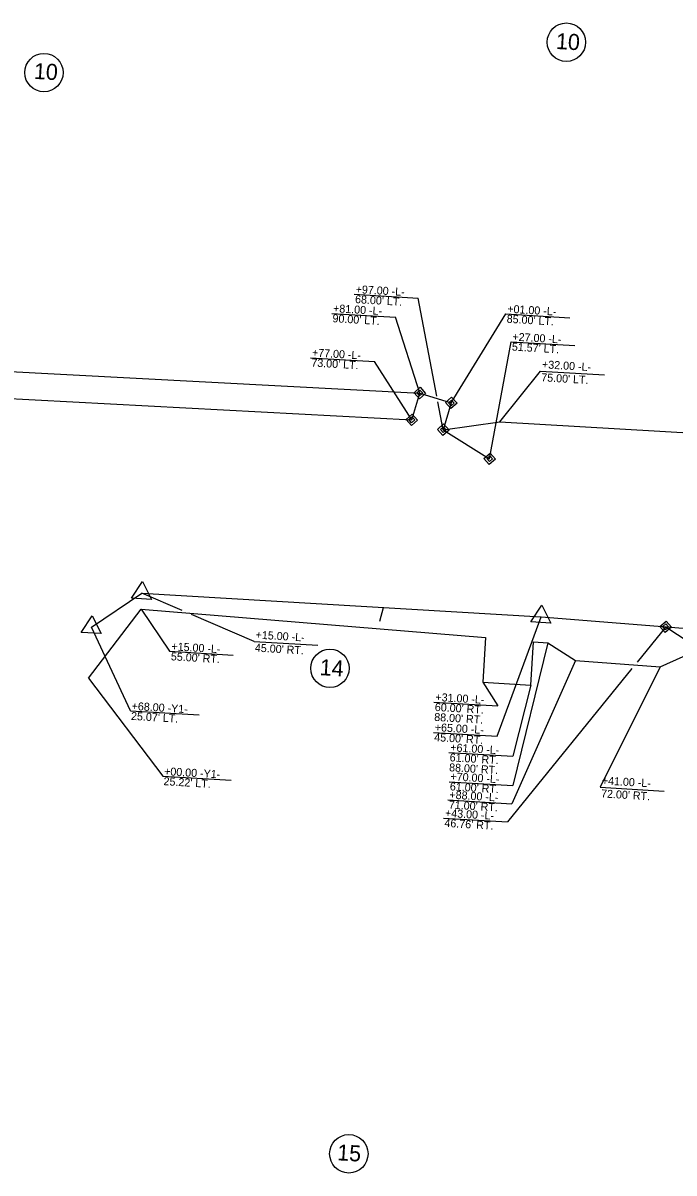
# Model space of a CAD drawing. Extents: x 2010883 to 2014849, y 442000 to 447413.
# Drawn here: x 2012375 to 2012782, y 444554 to 445272 of the extents above; entities that cross this region are included whole.
import ezdxf

# ---------------------------------------------------------------- set-up
doc = ezdxf.new("R2010")
doc.units = 0
for name, color, linetype in [('Old_Level_29', 7, 'Continuous'), ('Prop Easement Construction', 7, 'Continuous'), ('Prop Easement Construction Station Offsets', 7, 'Continuous'), ('Prop Easement Permanent Utility', 7, 'Continuous'), ('Prop Easement Permanent Utility Station Offsets', 7, 'Continuous'), ('Prop Parcel Number CELL', 7, 'Continuous'), ('Prop Parcel Number Text', 7, 'Continuous'), ('Prop ROW Marker CELL', 7, 'Continuous'), ('Prop ROW Permanent Easement CELL', 7, 'Continuous'), ('Prop ROW RW Lines', 7, 'Continuous'), ('Prop ROW Station Offsets', 7, 'Continuous')]:
    doc.layers.add(name, color=color, linetype=linetype)

msp = doc.modelspace()

# ---------------------------------------------------------------- linework, layer by layer
at = {"layer": 'Old_Level_29'}
msp.add_line((2012598.25, 444898.78), (2012600.7, 444907.31), dxfattribs=at)
at = {"layer": 'Prop Easement Construction'}
for p, q in [((2012296.76, 445058.46), (2012623.31, 445041.21)), ((2012637.99, 445018.31), (2012673.34, 445023.24)), ((2012673.34, 445023.24), (2012962.84, 445006.17)), ((2012416.2, 444862.98), (2012449.07, 444906.23)), ((2012449.07, 444906.23), (2012664.4, 444888.53)), ((2012664.4, 444888.53), (2012662.75, 444860.58)), ((2012692.7, 444858.81), (2012694.29, 444885.76)), ((2012694.29, 444885.76), (2012703.27, 444885.24)), ((2012703.27, 444885.24), (2012720.65, 444874.19)), ((2012773.5, 444870.08), (2012798.2, 444881.24)), ((2012720.65, 444874.19), (2012773.5, 444870.08)), ((2012662.75, 444860.58), (2012692.7, 444858.81))]:
    msp.add_line(p, q, dxfattribs=at)
at = {"layer": 'Prop Easement Construction Station Offsets'}
for p, q in [((2012673.34, 445023.24), (2012698.75, 445054.91)), ((2012698.75, 445054.91), (2012738.69, 445052.56)), ((2012449.07, 444906.23), (2012466.76, 444879.88)), ((2012703.27, 444885.24), (2012681.5, 444796.06)), ((2012466.76, 444879.88), (2012506.69, 444877.53)), ((2012720.65, 444874.19), (2012680.85, 444784.67)), ((2012773.5, 444870.08), (2012736.14, 444794.94)), ((2012416.2, 444862.98), (2012462.61, 444801.86)), ((2012662.75, 444860.58), (2012672.11, 444845.75)), ((2012692.7, 444858.81), (2012681.41, 444814.29)), ((2012632.18, 444848.1), (2012672.11, 444845.75)), ((2012641.48, 444816.64), (2012681.41, 444814.29)), ((2012462.61, 444801.86), (2012505.35, 444799.34)), ((2012641.57, 444798.42), (2012681.5, 444796.06)), ((2012736.14, 444794.94), (2012776.07, 444792.59)), ((2012640.92, 444787.02), (2012680.85, 444784.67))]:
    msp.add_line(p, q, dxfattribs=at)
at = {"layer": 'Prop Easement Permanent Utility'}
for p, q in [((2012300.75, 445041.19), (2012618.32, 445024.48)), ((2012618.32, 445024.48), (2012623.31, 445041.21)), ((2012623.31, 445041.21), (2012642.99, 445035.04)), ((2012642.99, 445035.04), (2012637.99, 445018.31)), ((2012637.99, 445018.31), (2012666.97, 445000.14)), ((2012776.99, 444895.16), (2012805.92, 444876.18))]:
    msp.add_line(p, q, dxfattribs=at)
at = {"layer": 'Prop Easement Permanent Utility Station Offsets'}
for p, q in [((2012582.33, 445102.87), (2012622.26, 445100.51)), ((2012633.98, 445039.29), (2012622.26, 445100.51)), ((2012568.22, 445090.94), (2012608.15, 445088.59)), ((2012623.31, 445041.21), (2012608.15, 445088.59)), ((2012642.99, 445035.04), (2012677.11, 445090.61)), ((2012677.11, 445090.61), (2012717.04, 445088.25)), ((2012666.97, 445000.14), (2012680.32, 445073.22)), ((2012680.32, 445073.22), (2012720.25, 445070.86)), ((2012555.01, 445063.28), (2012594.94, 445060.92)), ((2012618.32, 445024.48), (2012594.94, 445060.92)), ((2012637.99, 445018.31), (2012634.65, 445035.75)), ((2012776.99, 444895.16), (2012759.13, 444873.15)), ((2012755.83, 444869.08), (2012678.1, 444773.27)), ((2012638.17, 444775.62), (2012678.1, 444773.27))]:
    msp.add_line(p, q, dxfattribs=at)
at = {"layer": 'Prop Parcel Number CELL'}
for p, q in [((2012714.92, 445260.38), (2012714.92, 445260.38)), ((2012388.37, 445241.4), (2012388.37, 445241.4)), ((2012567.13, 444869.24), (2012567.13, 444869.24)), ((2012578.96, 444565.95), (2012578.96, 444565.95))]:
    msp.add_line(p, q, dxfattribs=at)
for centre in [(2012714.92, 445260.38), (2012388.37, 445241.4), (2012567.13, 444869.24), (2012578.96, 444565.95)]:
    msp.add_circle(centre, 12, dxfattribs=at)
at = {"layer": 'Prop ROW Marker CELL'}
for p, q in [((2012623.31, 445041.21), (2012623.31, 445041.21)), ((2012642.99, 445035.04), (2012642.99, 445035.04)), ((2012618.32, 445024.48), (2012618.32, 445024.48)), ((2012637.99, 445018.31), (2012637.99, 445018.31)), ((2012666.97, 445000.14), (2012666.97, 445000.14)), ((2012449.66, 444916.21), (2012449.66, 444916.21)), ((2012699.22, 444901.5), (2012699.22, 444901.5)), ((2012699.22, 444901.5), (2012699.22, 444901.5)), ((2012418.07, 444894.93), (2012418.07, 444894.93)), ((2012776.99, 444895.16), (2012776.99, 444895.16))]:
    msp.add_line(p, q, dxfattribs=at)
for points in [[(2012443.21, 444912.99), (2012450.08, 444923.4), (2012455.69, 444912.25)], [(2012692.77, 444898.28), (2012699.65, 444908.69), (2012705.25, 444897.54)], [(2012692.77, 444898.28), (2012699.65, 444908.69), (2012705.25, 444897.54)], [(2012411.61, 444891.7), (2012418.49, 444902.12), (2012424.09, 444890.97)]]:
    msp.add_lwpolyline(points, close=True, dxfattribs=at)
at = {"layer": 'Prop ROW Permanent Easement CELL'}
for points in [[(2012623.53, 445044.8), (2012626.91, 445041), (2012623.1, 445037.62), (2012619.72, 445041.42)], [(2012623.42, 445043.01), (2012625.11, 445041.1), (2012623.21, 445039.41), (2012621.52, 445041.32)], [(2012643.2, 445038.64), (2012646.58, 445034.83), (2012642.77, 445031.45), (2012639.39, 445035.25)], [(2012643.09, 445036.84), (2012644.78, 445034.94), (2012642.88, 445033.25), (2012641.19, 445035.15)], [(2012618.53, 445028.07), (2012621.91, 445024.26), (2012618.11, 445020.88), (2012614.73, 445024.69)], [(2012618.43, 445026.27), (2012620.12, 445024.37), (2012618.22, 445022.68), (2012616.52, 445024.58)], [(2012638.2, 445021.9), (2012641.59, 445018.1), (2012637.78, 445014.71), (2012634.4, 445018.52)], [(2012638.1, 445020.1), (2012639.79, 445018.2), (2012637.89, 445016.51), (2012636.2, 445018.41)], [(2012667.19, 445003.73), (2012670.57, 444999.93), (2012666.76, 444996.55), (2012663.38, 445000.35)], [(2012667.08, 445001.94), (2012668.77, 445000.03), (2012666.87, 444998.34), (2012665.18, 445000.25)], [(2012777.2, 444898.75), (2012780.58, 444894.95), (2012776.77, 444891.56), (2012773.39, 444895.37)], [(2012777.09, 444896.95), (2012778.78, 444895.05), (2012776.88, 444893.36), (2012775.19, 444895.26)]]:
    msp.add_lwpolyline(points, close=True, dxfattribs=at)
at = {"layer": 'Prop ROW RW Lines'}
for p, q in [((2012418.07, 444894.93), (2012449.66, 444916.21)), ((2012449.66, 444916.21), (2012699.22, 444901.5)), ((2012699.22, 444901.5), (2012920.55, 444883.45))]:
    msp.add_line(p, q, dxfattribs=at)
at = {"layer": 'Prop ROW Station Offsets'}
for p, q in [((2012474.79, 444905.39), (2012449.66, 444916.21)), ((2012519.74, 444886.03), (2012480.63, 444902.87)), ((2012671.73, 444826.87), (2012699.22, 444901.5)), ((2012442.52, 444842.64), (2012418.07, 444894.93)), ((2012519.74, 444886.03), (2012559.67, 444883.67)), ((2012442.52, 444842.64), (2012485.45, 444840.1)), ((2012631.8, 444829.22), (2012671.73, 444826.87))]:
    msp.add_line(p, q, dxfattribs=at)

# ---------------------------------------------------------------- texts
at = {"layer": 'Prop Easement Construction Station Offsets'}
for s, p in [('+32.00 -L-', (2012699.59, 445056.7)), ("75.00' LT.", (2012699.11, 445048.59)), ('+15.00 -L-', (2012467.97, 444880.51)), ("55.00' RT.", (2012467.6, 444874.27)), ('+31.00 -L-', (2012632.95, 444848.87)), ("60.00' RT.", (2012632.58, 444842.64)), ("88.00' RT.", (2012632.21, 444836.4)), ('+61.00 -L-', (2012642.25, 444817.41)), ("61.00' RT.", (2012641.88, 444811.17)), ('+00.00 -Y1-', (2012463.38, 444802.52)), ("88.00' RT.", (2012641.51, 444804.93)), ("25.22' LT.", (2012463.01, 444796.28)), ('+70.00 -L-', (2012642.35, 444799.28)), ('+41.00 -L-', (2012736.97, 444796.72)), ('+88.00 -L-', (2012641.7, 444787.85)), ("61.00' RT.", (2012641.98, 444793.04)), ("72.00' RT.", (2012736.5, 444788.61)), ("71.00' RT.", (2012641.33, 444781.61))]:
    msp.add_text(s, height=5, rotation=356.62643, dxfattribs=at).set_placement(p)
at = {"layer": 'Prop Easement Permanent Utility Station Offsets'}
for s, p in [('+97.00 -L-', (2012583.1, 445103.65)), ("68.00' LT.", (2012582.73, 445097.41)), ('+81.00 -L-', (2012568.99, 445091.72)), ('+01.00 -L-', (2012677.88, 445091.39)), ("90.00' LT.", (2012568.62, 445085.48)), ("85.00' LT.", (2012677.51, 445085.15)), ("51.57' LT.", (2012680.73, 445067.76)), ('+27.00 -L-', (2012681.09, 445074)), ('+77.00 -L-', (2012555.78, 445064.06)), ("73.00' LT.", (2012555.41, 445057.82)), ('+43.00 -L-', (2012638.94, 444776.44)), ("46.76' RT.", (2012638.58, 444770.2))]:
    msp.add_text(s, height=5, rotation=356.62643, dxfattribs=at).set_placement(p)
at = {"layer": 'Prop Parcel Number Text'}
for s, p in [('10', (2012708.22, 445256.18)), ('10', (2012381.91, 445237.5)), ('14', (2012560.58, 444865)), ('15', (2012571.48, 444561.91))]:
    msp.add_text(s, height=10, rotation=356.62643, dxfattribs=at).set_placement(p)
at = {"layer": 'Prop ROW Station Offsets'}
for s, p in [('+15.00 -L-', (2012520.58, 444887.81)), ("45.00' RT.", (2012520.1, 444879.7)), ("25.07' LT.", (2012442.7, 444837.03)), ('+68.00 -Y1-', (2012443.07, 444843.27)), ('+65.00 -L-', (2012632.57, 444830.05)), ("45.00' RT.", (2012632.21, 444823.81))]:
    msp.add_text(s, height=5, rotation=356.62643, dxfattribs=at).set_placement(p)

doc.saveas('drawing.dxf')
